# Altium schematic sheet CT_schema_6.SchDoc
size 411 x 382 mm
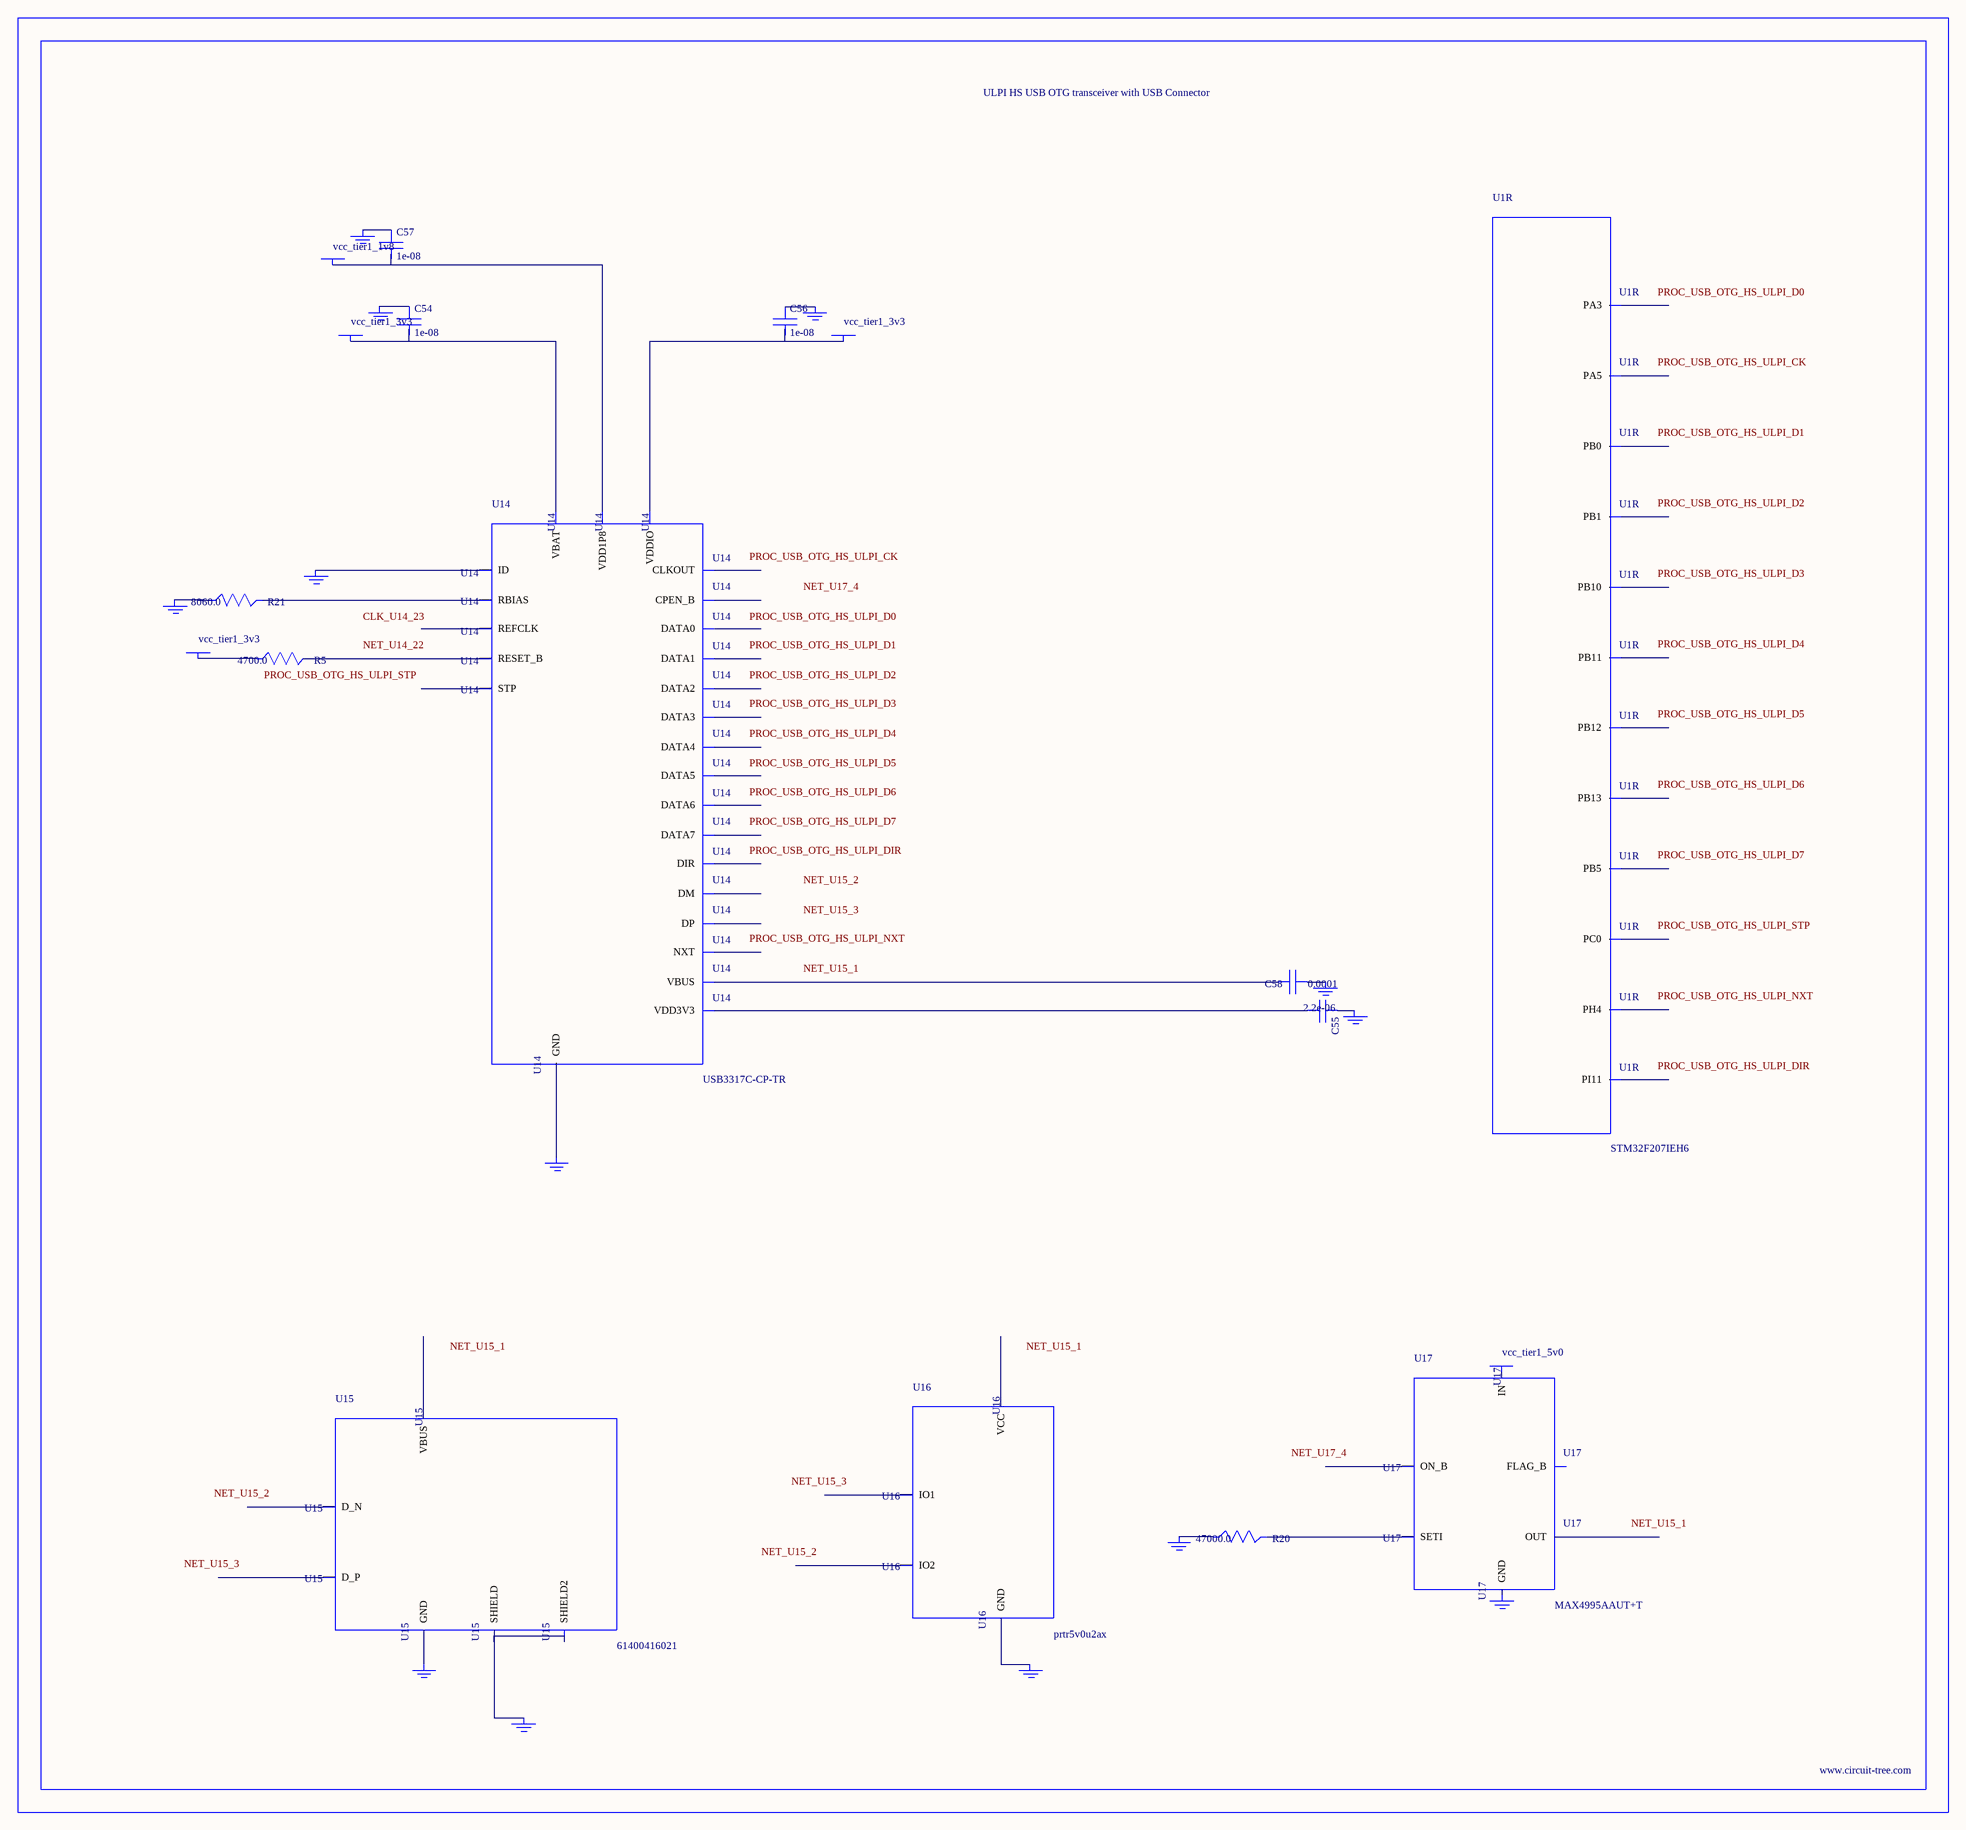
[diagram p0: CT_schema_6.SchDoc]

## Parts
BORDER5  (no value)
C54  1e-08  [C0402]
C55  2.2e-06  [C0603]
C56  1e-08  [C0402]
C57  1e-08  [C0402]
C58  0.0001  [R0603]
GND_INSTANCE_5_0  (no value)
GND_INSTANCE_5_1  (no value)
GND_INSTANCE_5_2  (no value)
GND_INSTANCE_5_3  (no value)
GND_INSTANCE_5_4  (no value)
GND_INSTANCE_5_5  (no value)
GND_INSTANCE_5_6  (no value)
GND_INSTANCE_5_7  (no value)
GND_INSTANCE_5_8  (no value)
GND_INSTANCE_5_9  (no value)
GND_INSTANCE_5_10  (no value)
GND_INSTANCE_5_11  (no value)
GND_INSTANCE_5_12  (no value)
POWER_INSTANCE_5_0  vcc_tier1_3v3
POWER_INSTANCE_5_1  vcc_tier1_3v3
POWER_INSTANCE_5_2  vcc_tier1_1v8
POWER_INSTANCE_5_3  vcc_tier1_3v3
POWER_INSTANCE_5_4  vcc_tier1_5v0
R5  4700.0  [R0603]
R20  47000.0  [R0603]
R21  8060.0  [R0603]
U1  STM32F207IEH6  [UFBGA176_25]  (part R of 18)
U14  USB3317C-CP-TR  [QFN-24]
U15  61400416021  [USB-A-H]
U16  prtr5v0u2ax  [SOT143B]
U17  MAX4995AAUT+T  [SOT-23-6]

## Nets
NetC54_1: C54.1 GND_INSTANCE_5_2.0(GND)
NetC54_2: C54.2 POWER_INSTANCE_5_0.0(PWR) U14.3(VBAT)
NetC55_1: C55.1 GND_INSTANCE_5_3.0(GND)
NetC55_2: C55.2 U14.4(VDD3V3)
NetC56_1: C56.1 GND_INSTANCE_5_4.0(GND)
NetC56_2: C56.2 POWER_INSTANCE_5_1.0(PWR) U14.17(VDDIO)
NetC57_1: C57.1 GND_INSTANCE_5_5.0(GND)
NetC57_2: C57.2 POWER_INSTANCE_5_2.0(PWR) U14.21(VDD1P8)
NetC58_1: C58.1 GND_INSTANCE_5_1.0(GND)
NetC58_2: C58.2 U14.2(VBUS)
NetGND_INSTANCE_5_0_0: GND_INSTANCE_5_0.0(GND) U14.1(ID)
NetGND_INSTANCE_5_6_0: GND_INSTANCE_5_6.0(GND) R21.1
NetGND_INSTANCE_5_7_0: GND_INSTANCE_5_7.0(GND) U14.25(GND)
NetGND_INSTANCE_5_8_0: GND_INSTANCE_5_8.0(GND) U15.5(SHIELD) U15.6(SHIELD2)
NetGND_INSTANCE_5_9_0: GND_INSTANCE_5_9.0(GND) U15.4(GND)
NetGND_INSTANCE_5_10_0: GND_INSTANCE_5_10.0(GND) U16.1(GND)
NetGND_INSTANCE_5_11_0: GND_INSTANCE_5_11.0(GND) R20.1
NetPOWER_INSTANCE_5_3_0: POWER_INSTANCE_5_3.0(PWR) R5.1
NetR5_2: R5.2 U14.22(RESET_B)
NetR20_2: R20.2 U17.3(SETI)
NetR21_2: R21.2 U14.24(RBIAS)

Not connected (* = marked no-connect by the designer): GND_INSTANCE_5_12 0(GND); POWER_INSTANCE_5_4 0(PWR); U1 A6(PB5) E4(PI11) H4(PH4) M2(PC0) P4(PA5) P12(PB12) P13(PB13) R2(PA3) R4(PB1) R5(PB0) R12(PB10) R13(PB11); U14 5(DM) 6(DP) 7(CPEN_B) 8(DATA7) 9(DATA6) 10(DATA5) 11(DATA4) 12(CLKOUT) 13(DATA3) 14(DATA2) 15(DATA1) 16(DATA0) 18(NXT) 19(DIR) 20(STP) 23(REFCLK); U15 1(VBUS) 2(D_N) 3(D_P); U16 2(IO1) 3(IO2) 4(VCC); U17 1(OUT) 2(GND) 4(ON_B) 5(IN) 6(FLAG_B)

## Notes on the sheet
- Labels drawn without touching a wire or pin: CLK_U14_23, NET_U14_22, NET_U15_1, NET_U15_2, NET_U15_3, NET_U17_4, PROC_USB_OTG_HS_ULPI_CK, PROC_USB_OTG_HS_ULPI_D0, PROC_USB_OTG_HS_ULPI_D1, PROC_USB_OTG_HS_ULPI_D2, PROC_USB_OTG_HS_ULPI_D3, PROC_USB_OTG_HS_ULPI_D4, PROC_USB_OTG_HS_ULPI_D5, PROC_USB_OTG_HS_ULPI_D6, PROC_USB_OTG_HS_ULPI_D7, PROC_USB_OTG_HS_ULPI_DIR, PROC_USB_OTG_HS_ULPI_NXT, PROC_USB_OTG_HS_ULPI_STP

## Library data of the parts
BORDER5 = BORDER_PAGE5
C54 C56 C57 = C0402C103K3RAC
C55 = C0603C225K8RACTU
C58 = C58
GND_INSTANCE_5_0-GND_INSTANCE_5_12 = GND
POWER_INSTANCE_5_0-POWER_INSTANCE_5_4 = PWR
R5 = RC0603JR-074K7L
R20 = RC0603JR-0747KL
R21 = ERJ-3EKF8061V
